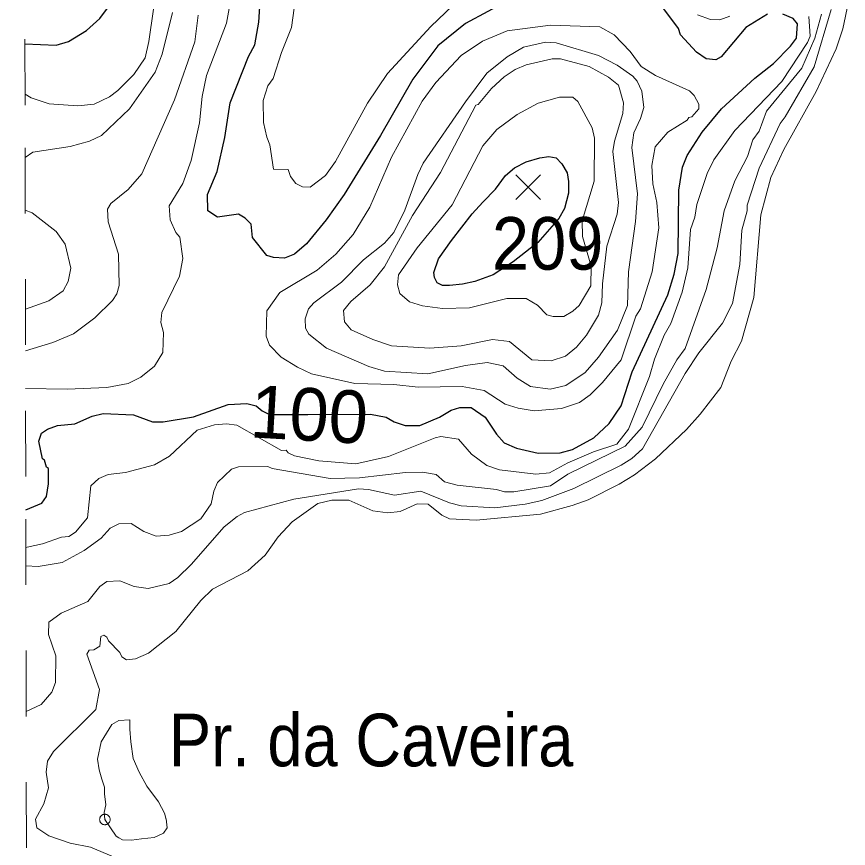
# Model space of a CAD drawing. Extents: x 474.5 to 500, y 7345.7 to 7373.4.
# Drawn here: x 474.522 to 475.788, y 7364.921 to 7366.186 of the extents above; entities that cross this region are included whole.
import ezdxf
from ezdxf.enums import TextEntityAlignment as Align

# ---------------------------------------------------------------- set-up
doc = ezdxf.new("R2010")
doc.units = 0
doc.header["$LTSCALE"] = 0.032
doc.header["$PDMODE"] = 32
doc.header["$PDSIZE"] = 0.016
doc.linetypes.add('SHORT_DASHED', pattern=[2.7, 1.5, -1.2])
for name, color, linetype, lineweight in [('1', 7, 'Continuous', 25), ('15', 7, 'SHORT_DASHED', 13), ('16', 7, 'SHORT_DASHED', 13), ('2', 7, 'Continuous', 13), ('21', 7, 'Continuous', 25), ('22', 7, 'SHORT_DASHED', 13)]:
    doc.layers.add(name, color=color, linetype=linetype, lineweight=lineweight)
doc.layers.add('61', color=7, linetype='Continuous')

msp = doc.modelspace()

# ---------------------------------------------------------------- linework, layer by layer
at = {"layer": '1'}
for points in [[(475.2732, 7366.2123), (475.2053, 7366.1753), (475.1632, 7366.1409), (475.1249, 7366.0905), (475.0758, 7366.0047), (475.0204, 7365.915), (474.9933, 7365.8767), (474.9633, 7365.8398), (474.9447, 7365.8245), (474.9298, 7365.8184), (474.913, 7365.8191), (474.903, 7365.8223), (474.8808, 7365.8497), (474.8788, 7365.8698), (474.8698, 7365.8791), (474.8597, 7365.8852), (474.828, 7365.8806), (474.8129, 7365.89), (474.8126, 7365.915), (474.8271, 7365.9498), (474.8389, 7366.0018), (474.847, 7366.0547), (474.875, 7366.1249), (474.8845, 7366.1425), (474.8907, 7366.177), (474.8951, 7366.2488)], [(474.5349, 7366.1443), (474.5823, 7366.1423), (474.6012, 7366.1478), (474.6287, 7366.1644), (474.6489, 7366.1826), (474.6622, 7366.2006)], [(475.6647, 7366.1894), (475.6316, 7366.1689), (475.5942, 7366.1245), (475.5861, 7366.1199), (475.5713, 7366.1215), (475.5567, 7366.1313), (475.5323, 7366.1579), (475.5289, 7366.1677), (475.5051, 7366.1993)], [(474.5362, 7365.4356), (474.5607, 7365.4454), (474.5677, 7365.4556), (474.5708, 7365.4749), (474.5708, 7365.4981), (474.5677, 7365.5003), (474.5645, 7365.511), (474.5613, 7365.5132), (474.5558, 7365.5401), (474.56, 7365.552), (474.569, 7365.5581), (474.5845, 7365.5638), (474.6109, 7365.5663), (474.6373, 7365.5779), (474.6538, 7365.5821), (474.7001, 7365.5797), (474.7289, 7365.5695), (474.7451, 7365.5695), (474.7914, 7365.577), (474.8438, 7365.5957), (474.8724, 7365.5973), (474.8866, 7365.5934), (474.8957, 7365.586), (474.9068, 7365.5806), (474.9652, 7365.5807), (475.0607, 7365.5808), (475.0846, 7365.5765), (475.0965, 7365.5692), (475.1133, 7365.5639), (475.1356, 7365.5638), (475.1654, 7365.5762), (475.1831, 7365.5868), (475.1963, 7365.5909), (475.2135, 7365.5909), (475.2348, 7365.5762), (475.2524, 7365.5503), (475.2641, 7365.5375), (475.2828, 7365.5294), (475.3157, 7365.5216), (475.3492, 7365.5223), (475.3677, 7365.5274), (475.4003, 7365.5451), (475.4237, 7365.567), (475.442, 7365.5934), (475.4584, 7365.6454), (475.5131, 7365.7627), (475.5226, 7365.794), (475.5288, 7365.8251), (475.5297, 7365.9217), (475.5352, 7365.9564), (475.5424, 7365.9744), (475.565, 7366.01), (475.5946, 7366.0451), (475.6454, 7366.0919), (475.6736, 7366.1144), (475.6996, 7366.1404), (475.7084, 7366.1528), (475.71, 7366.1746), (475.7036, 7366.1828), (475.6877, 7366.1892)]]:
    msp.add_lwpolyline(points, dxfattribs=at)
msp.add_lwpolyline([(475.1837, 7365.8451), (475.2153, 7365.8856), (475.2312, 7365.9034), (475.2509, 7365.9232), (475.2658, 7365.9439), (475.2796, 7365.9558), (475.2974, 7365.9647), (475.3182, 7365.9706), (475.332, 7365.9726), (475.3429, 7365.9706), (475.3518, 7365.9617), (475.3597, 7365.9479), (475.3617, 7365.935), (475.3617, 7365.9172), (475.3557, 7365.8935), (475.3468, 7365.8787), (475.3152, 7365.8421), (475.2776, 7365.8124), (475.247, 7365.7927), (475.2193, 7365.7828), (475.2005, 7365.7788), (475.1807, 7365.7768), (475.1699, 7365.7768), (475.1619, 7365.7808), (475.158, 7365.7887), (475.157, 7365.7966), (475.1639, 7365.8174)], close=True, dxfattribs=at)
at = {"layer": '15'}
msp.add_line((474.7497, 7364.9647), (474.7497, 7364.9655), dxfattribs=at)
for points in [[(474.6946, 7365.116), (474.6775, 7365.1151), (474.6672, 7365.1092), (474.651, 7365.0826), (474.6451, 7365.0561), (474.648, 7365.0399), (474.6517, 7365.026), (474.6557, 7365.0137), (474.6561, 7365.0035), (474.6579, 7364.9867), (474.6554, 7364.975), (474.6565, 7364.9646)], [(474.738, 7364.9916), (474.7205, 7365.0154), (474.7088, 7365.0363), (474.6996, 7365.0571), (474.6959, 7365.0826), (474.6946, 7365.1018), (474.6946, 7365.116)], [(474.7497, 7364.9647), (474.747, 7364.9739), (474.738, 7364.9916)], [(474.6565, 7364.9645), (474.6734, 7364.9391), (474.6776, 7364.9366), (474.6831, 7364.9338), (474.6967, 7364.9333), (474.7122, 7364.9351), (474.7316, 7364.9373), (474.7457, 7364.9435), (474.751, 7364.9519), (474.7497, 7364.9655)]]:
    msp.add_lwpolyline(points, dxfattribs=at)
at = {"layer": '16'}
msp.add_line((474.6565, 7364.9645), (474.6565, 7364.9646), dxfattribs=at)
msp.add_point((474.6565, 7364.9645), dxfattribs=at)
at = {"layer": '2'}
for points in [[(474.7369, 7366.243), (474.7233, 7366.1476), (474.7176, 7366.1231), (474.7003, 7366.0978), (474.6763, 7366.073), (474.6636, 7366.0634), (474.64, 7366.0522), (474.6153, 7366.0497), (474.5716, 7366.0529), (474.5442, 7366.0622), (474.5351, 7366.0676)], [(474.5359, 7365.6199), (474.5992, 7365.6188), (474.6592, 7365.6213), (474.6918, 7365.6276), (474.7111, 7365.6371), (474.7318, 7365.6538), (474.7444, 7365.6748), (474.7456, 7365.705), (474.7417, 7365.7205), (474.7429, 7365.7356), (474.7699, 7365.7906), (474.7751, 7365.8178), (474.7705, 7365.8504), (474.7644, 7365.8572), (474.7558, 7365.8763), (474.7544, 7365.8978), (474.7751, 7365.9316), (474.7879, 7365.967), (474.8006, 7366.0241), (474.8047, 7366.0643), (474.8111, 7366.0962), (474.8413, 7366.1755), (474.8485, 7366.2154)], [(474.6893, 7365.2073), (474.703, 7365.209), (474.7227, 7365.2173), (474.7645, 7365.2502), (474.8024, 7365.2975), (474.8203, 7365.3147), (474.8738, 7365.3427), (474.9002, 7365.3665), (474.9199, 7365.3944), (474.9414, 7365.4174), (474.9803, 7365.4453), (475.0015, 7365.4504), (475.0276, 7365.4503), (475.0642, 7365.4338), (475.0869, 7365.4307), (475.1057, 7365.4331), (475.1316, 7365.4447), (475.1485, 7365.4439), (475.169, 7365.4276), (475.1807, 7365.422), (475.2212, 7365.4195), (475.3189, 7365.429), (475.3673, 7365.4418), (475.3918, 7365.4509), (475.4388, 7365.4744), (475.4619, 7365.4886), (475.494, 7365.5129), (475.5411, 7365.5576), (475.5623, 7365.5811), (475.5933, 7365.6215), (475.6093, 7365.6614), (475.6248, 7365.6919), (475.6439, 7365.7582), (475.6543, 7365.8843), (475.6693, 7365.9409), (475.6891, 7365.9837), (475.7387, 7366.0718), (475.7687, 7366.1367), (475.7792, 7366.1668), (475.7875, 7366.2079)], [(474.9442, 7366.1986), (474.9402, 7366.1691), (474.9249, 7366.1308), (474.9124, 7366.0914), (474.9045, 7366.0802), (474.8972, 7366.058), (474.8979, 7366.0244), (474.9026, 7366.0024), (474.9076, 7365.9904), (474.9132, 7365.9536), (474.9351, 7365.9531), (474.9388, 7365.9425), (474.9467, 7365.9317), (474.9571, 7365.9269), (474.9686, 7365.9263), (474.9919, 7365.9441), (475.0074, 7365.9654), (475.0558, 7366.0542), (475.0864, 7366.0993), (475.1522, 7366.1707), (475.1859, 7366.2027)], [(474.5352, 7365.9712), (474.5466, 7365.9792), (474.6035, 7365.988), (474.6329, 7365.9961), (474.6512, 7366.0048), (474.6941, 7366.0453), (474.7327, 7366.1013), (474.7435, 7366.1287), (474.7592, 7366.1919)], [(474.5363, 7365.3501), (474.5548, 7365.3491), (474.5914, 7365.3556), (474.6249, 7365.3738), (474.6508, 7365.3925), (474.6646, 7365.4077), (474.6779, 7365.4143), (474.6962, 7365.4146), (474.7157, 7365.4024), (474.7347, 7365.3956), (474.7541, 7365.3971), (474.773, 7365.4024), (474.8024, 7365.422), (474.8181, 7365.4447), (474.8222, 7365.4641), (474.8279, 7365.477), (474.8492, 7365.4975), (474.8599, 7365.5009), (474.9045, 7365.5016), (474.9107, 7365.4983), (474.9992, 7365.4833), (475.0436, 7365.4841), (475.1137, 7365.492), (475.1395, 7365.4928), (475.1606, 7365.489), (475.1732, 7365.4781), (475.1926, 7365.4729), (475.2521, 7365.4665), (475.2645, 7365.4626), (475.2786, 7365.4626), (475.3343, 7365.4722), (475.3605, 7365.4899), (475.4477, 7365.5322), (475.4738, 7365.5612), (475.5057, 7365.6266), (475.5268, 7365.6637), (475.5394, 7365.6806), (475.5713, 7365.7707), (475.588, 7365.834), (475.5985, 7365.8904), (475.6147, 7365.9358), (475.6342, 7365.9728), (475.6424, 7365.9982), (475.6518, 7366.0113), (475.663, 7366.0416), (475.7166, 7366.1074), (475.7365, 7366.1528), (475.7466, 7366.1892)], [(475.7276, 7366.1857), (475.7292, 7366.156), (475.7253, 7366.1464), (475.6865, 7366.0871), (475.6147, 7366.0125), (475.583, 7365.9676), (475.5726, 7365.947), (475.557, 7365.8999), (475.5537, 7365.8805), (475.5475, 7365.862), (475.5433, 7365.8034), (475.5349, 7365.7666), (475.5174, 7365.7188), (475.5072, 7365.7013), (475.4925, 7365.6646), (475.4852, 7365.6383), (475.4531, 7365.558), (475.4353, 7365.5352), (475.3999, 7365.5235), (475.3606, 7365.5071), (475.3329, 7365.4916), (475.3123, 7365.4897), (475.2568, 7365.4965), (475.2373, 7365.5027), (475.2144, 7365.5201), (475.1942, 7365.5427), (475.1677, 7365.547), (475.1587, 7365.5452), (475.0878, 7365.5167), (475.0381, 7365.5056), (474.9819, 7365.5102), (474.9448, 7365.5177), (474.9352, 7365.522), (474.9321, 7365.5262), (474.9249, 7365.5257), (474.8571, 7365.5644), (474.8417, 7365.5663), (474.8232, 7365.5647), (474.7968, 7365.5567), (474.7545, 7365.5169), (474.7318, 7365.5039), (474.6879, 7365.4921), (474.6612, 7365.4891), (474.6474, 7365.4832), (474.6349, 7365.4722), (474.6298, 7365.4233), (474.6117, 7365.4014), (474.6014, 7365.3949), (474.5904, 7365.3939), (474.5613, 7365.3835), (474.5382, 7365.3788), (474.5363, 7365.3784)], [(475.7611, 7366.1964), (475.7357, 7366.109), (475.6914, 7366.033), (475.6836, 7366.0231), (475.6517, 7365.9553), (475.6337, 7365.8987), (475.6335, 7365.8902), (475.6252, 7365.8609), (475.6223, 7365.8085), (475.6112, 7365.7494), (475.5959, 7365.7192), (475.5599, 7365.674), (475.5392, 7365.6426), (475.4741, 7365.5282), (475.4581, 7365.5134), (475.4419, 7365.5032), (475.3699, 7365.4678), (475.321, 7365.4498), (475.2959, 7365.444), (475.2498, 7365.4386), (475.1984, 7365.4414), (475.1807, 7365.4462), (475.1373, 7365.4641), (475.0972, 7365.4578), (475.0573, 7365.4666), (475.0421, 7365.4674), (474.9441, 7365.4515), (474.8687, 7365.4312), (474.8575, 7365.4254), (474.8379, 7365.4096), (474.7878, 7365.3523), (474.7673, 7365.3325), (474.7544, 7365.3234), (474.7223, 7365.3158), (474.7011, 7365.3191), (474.679, 7365.3277), (474.6592, 7365.3263), (474.649, 7365.3189), (474.6307, 7365.2959), (474.5898, 7365.2781), (474.5714, 7365.2647), (474.5708, 7365.2457), (474.582, 7365.2136), (474.5811, 7365.1731), (474.5755, 7365.1583), (474.5597, 7365.1396), (474.5367, 7365.129)], [(474.7982, 7366.1879), (474.7934, 7366.147), (474.7623, 7366.0592)], [(475.5578, 7366.1885), (475.5779, 7366.1812), (475.5922, 7366.1805), (475.6073, 7366.1862)], [(474.7623, 7366.0592), (474.7126, 7365.9465), (474.6921, 7365.9229), (474.6653, 7365.9015), (474.6603, 7365.8925), (474.6616, 7365.8735), (474.677, 7365.8245), (474.6784, 7365.7766), (474.6747, 7365.7639), (474.668, 7365.7536), (474.6411, 7365.7273), (474.6089, 7365.7033), (474.5775, 7365.6899), (474.5358, 7365.6775)], [(474.5356, 7365.7405), (474.5711, 7365.7534), (474.5928, 7365.7685), (474.6005, 7365.7826), (474.6044, 7365.8029), (474.5961, 7365.8394), (474.5821, 7365.8589), (474.546, 7365.8873), (474.5354, 7365.891)], [(474.6983, 7364.8954), (474.6345, 7364.9225), (474.6037, 7364.9286), (474.5714, 7364.9397), (474.5529, 7364.9517), (474.551, 7364.965), (474.5636, 7364.9884), (474.5708, 7365.0128), (474.567, 7365.0363), (474.569, 7365.0533), (474.5785, 7365.068), (474.6426, 7365.1317), (474.6482, 7365.1622), (474.6292, 7365.216), (474.6323, 7365.2221), (474.6394, 7365.2226), (474.6489, 7365.228), (474.6504, 7365.2427), (474.6548, 7365.2448), (474.6596, 7365.242), (474.6618, 7365.2362), (474.679, 7365.2187), (474.6822, 7365.2117), (474.6893, 7365.2073)]]:
    msp.add_lwpolyline(points, dxfattribs=at)
for points in [[(475.1998, 7365.6229), (475.1332, 7365.6221), (475.0961, 7365.626), (475.0365, 7365.6277), (474.9707, 7365.6425), (474.9497, 7365.6523), (474.9246, 7365.6679), (474.907, 7365.6858), (474.9019, 7365.6995), (474.9026, 7365.738), (474.9225, 7365.7662), (474.9793, 7365.7999), (475.0077, 7365.8243), (475.0343, 7365.8542), (475.0596, 7365.8958), (475.0927, 7365.9717), (475.1393, 7366.0571), (475.1597, 7366.0855), (475.1984, 7366.1266), (475.2311, 7366.148), (475.2684, 7366.1638), (475.3346, 7366.1725), (475.4095, 7366.17), (475.4313, 7366.1577), (475.4556, 7366.1326), (475.4722, 7366.1097), (475.4943, 7366.096), (475.546, 7366.0726), (475.553, 7366.0655), (475.5601, 7366.0526), (475.5598, 7366.0453), (475.5496, 7366.033), (475.545, 7366.032), (475.5423, 7366.0281), (475.513, 7366.0096), (475.4934, 7365.9875), (475.4884, 7365.9594), (475.49, 7365.9314), (475.4962, 7365.9028), (475.4994, 7365.8643), (475.4891, 7365.7973), (475.4711, 7365.7411), (475.4641, 7365.73), (475.4421, 7365.6638), (475.4133, 7365.6292), (475.3946, 7365.6106), (475.3785, 7365.5987), (475.3513, 7365.5894), (475.3096, 7365.5858), (475.285, 7365.5899), (475.2655, 7365.5963), (475.2333, 7365.6171)], [(475.2378, 7365.6595), (475.2049, 7365.6548), (475.1477, 7365.6421), (475.0819, 7365.6463), (475.0578, 7365.6536), (474.9935, 7365.6813), (474.9666, 7365.7028), (474.9617, 7365.7117), (474.9611, 7365.7261), (474.9663, 7365.7412), (474.9745, 7365.7504), (475.0162, 7365.7818), (475.0501, 7365.8157), (475.0818, 7365.841), (475.0962, 7365.8571), (475.1129, 7365.891), (475.1325, 7365.9457), (475.1409, 7365.9628), (475.2049, 7366.0561), (475.2374, 7366.0995), (475.2686, 7366.1242), (475.2933, 7366.1393), (475.3269, 7366.1469), (475.3429, 7366.1455), (475.4076, 7366.1266), (475.4359, 7366.1117), (475.4595, 7366.0952), (475.4662, 7366.0874), (475.4731, 7366.072), (475.4762, 7366.0475), (475.4715, 7366.0305), (475.4612, 7366.0086), (475.458, 7365.9867), (475.4668, 7365.916), (475.4635, 7365.8739), (475.4528, 7365.7972), (475.4516, 7365.746), (475.4365, 7365.7085), (475.4072, 7365.6675), (475.3869, 7365.6445), (475.3577, 7365.6246), (475.3338, 7365.6189), (475.3041, 7365.6229), (475.2834, 7365.6356), (475.2626, 7365.6546)], [(475.2462, 7365.6943), (475.1985, 7365.6851), (475.151, 7365.6812), (475.0926, 7365.6851), (475.0639, 7365.6946), (475.0312, 7365.7092), (475.0208, 7365.7213), (475.0193, 7365.7385), (475.0304, 7365.7521), (475.0599, 7365.7776), (475.0816, 7365.8049), (475.1242, 7365.8832), (475.1672, 7365.9485), (475.221, 7366.051), (475.2245, 7366.0517), (475.2447, 7366.0765), (475.2638, 7366.0939), (475.2806, 7366.105), (475.2975, 7366.1123), (475.3367, 7366.1214), (475.3495, 7366.1214), (475.3932, 7366.1099), (475.4227, 7366.0937), (475.438, 7366.0814), (475.4452, 7366.0546), (475.4442, 7366.0383), (475.4318, 7365.9964), (475.4293, 7365.9804), (475.438, 7365.9028), (475.4357, 7365.8851), (475.4199, 7365.8364), (475.4134, 7365.779), (475.4126, 7365.7503), (475.4073, 7365.7315), (475.3889, 7365.7013), (475.3737, 7365.6831), (475.3572, 7365.6692), (475.3354, 7365.662), (475.3062, 7365.6636), (475.272, 7365.6914)], [(475.2678, 7365.7567), (475.2113, 7365.7426), (475.1699, 7365.7418), (475.1398, 7365.7455), (475.1198, 7365.752), (475.1053, 7365.7643), (475.1017, 7365.7779), (475.1031, 7365.793), (475.1313, 7365.8339), (475.1848, 7365.8991), (475.2316, 7365.9892), (475.2525, 7366.0141), (475.2838, 7366.0368), (475.3155, 7366.0542), (475.3482, 7366.0633), (475.3684, 7366.0632), (475.3761, 7366.0563), (475.398, 7366.0164), (475.4013, 7366.0008), (475.4006, 7365.9354), (475.3823, 7365.8751), (475.3832, 7365.851), (475.3963, 7365.8061), (475.3957, 7365.7763), (475.3781, 7365.7464), (475.3685, 7365.7374), (475.3548, 7365.7297), (475.3384, 7365.7296), (475.3288, 7365.7322), (475.3144, 7365.7465), (475.2974, 7365.7568)]]:
    msp.add_lwpolyline(points, close=True, dxfattribs=at)
at = {"layer": '21'}
for p, q in [((475.2816, 7365.9451), (475.3191, 7365.9076)), ((475.3191, 7365.9451), (475.2816, 7365.9076))]:
    msp.add_line(p, q, dxfattribs=at)
at = {"layer": '22'}
msp.add_lwpolyline([(474.5381, 7364.3565), (474.5371, 7364.9213), (474.5361, 7365.4862), (474.5351, 7366.0511), (474.5341, 7366.616), (474.5331, 7367.1808), (474.5321, 7367.7457), (474.5311, 7368.3105), (474.5301, 7368.8754), (474.5291, 7369.4403), (474.5281, 7370.0051), (474.5272, 7370.57), (474.5262, 7371.1349), (474.5252, 7371.6997), (474.5242, 7372.2646), (474.5232, 7372.8295), (474.5222, 7373.3943)], dxfattribs=at)

# ---------------------------------------------------------------- texts
at = {"layer": '61'}
for s, width, p in [('209', 0.95, (475.33, 7365.8007)), ('Pr. da Caveira', 0.9, (475.0616, 7365.0454))]:
    msp.add_text(s, height=0.08, dxfattribs=dict(at, width=width)).set_placement(p, align=Align.CENTER)
msp.add_text('100', height=0.08, rotation=356.74, dxfattribs=at).set_placement((474.9651, 7365.5407), align=Align.CENTER)

doc.saveas('drawing.dxf')
